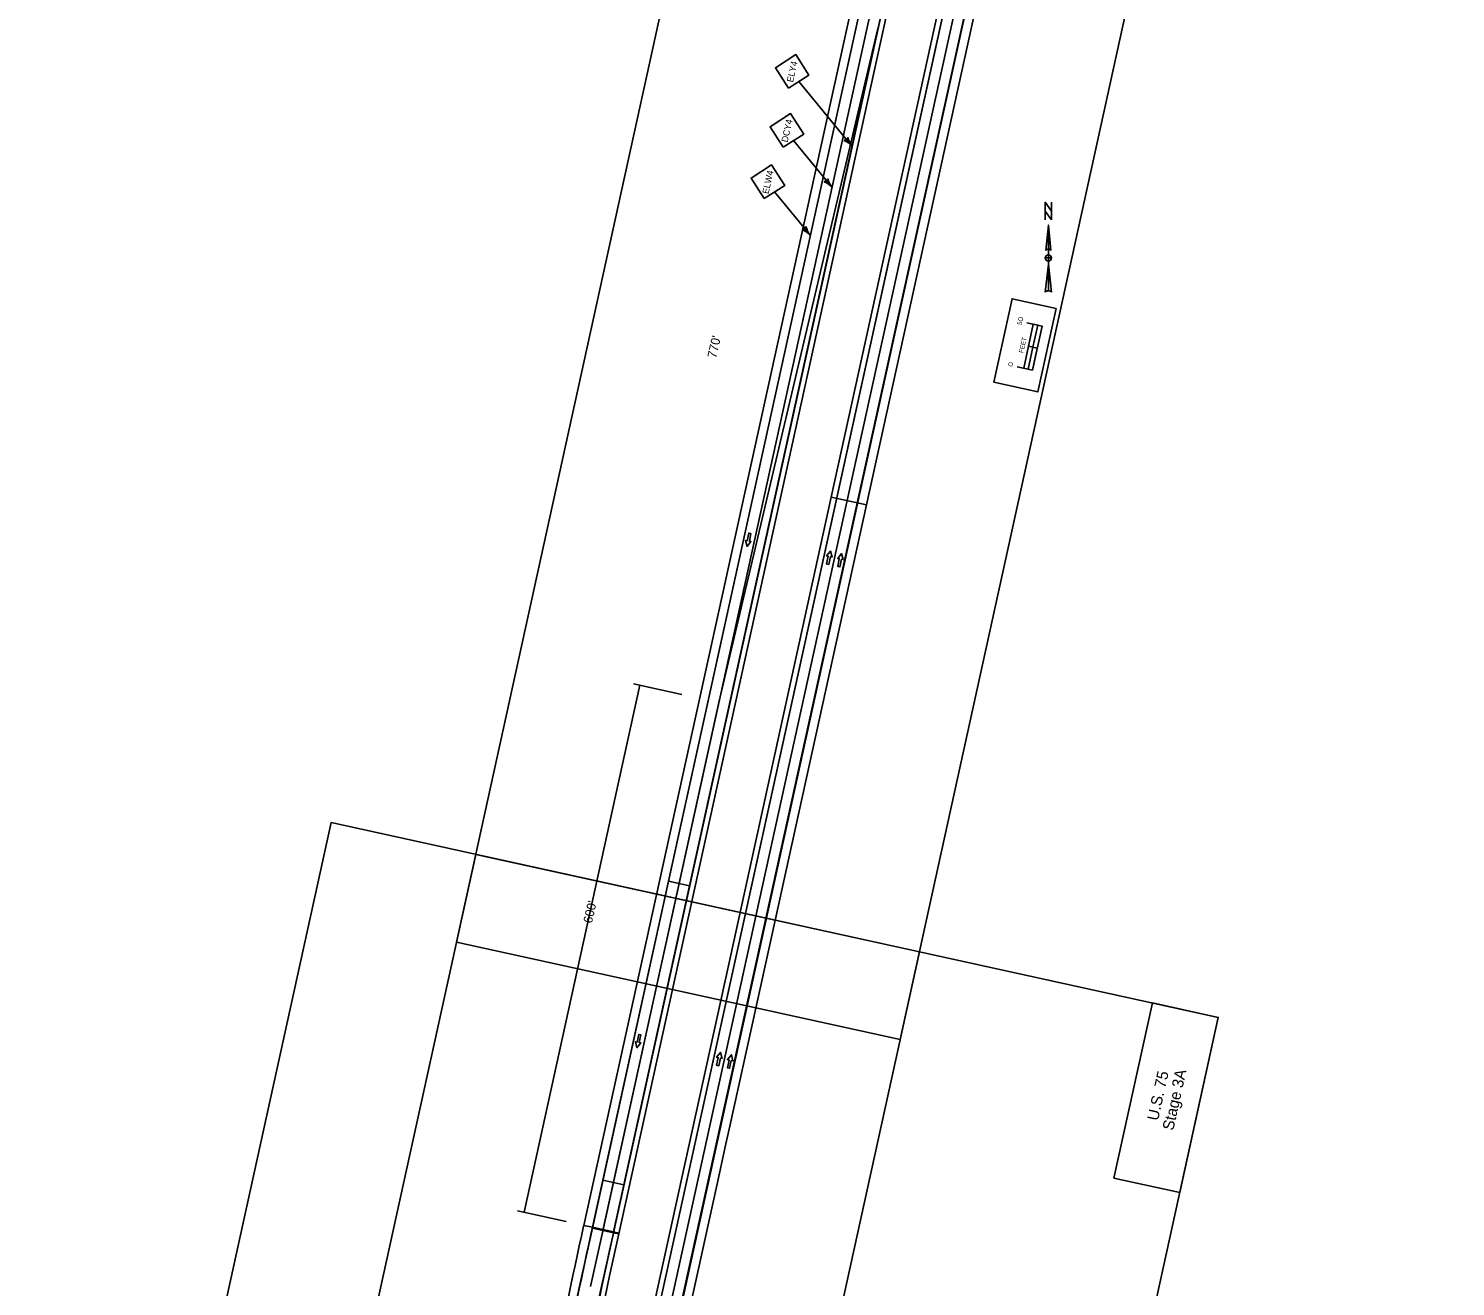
# Model space of a CAD drawing. Extents: x 14104283 to 14129344, y 8637090 to 8673339.
# Drawn here: x 14107490 to 14109077, y 8640895 to 8642294 of the extents above; entities that cross this region are included whole.
import ezdxf

# ---------------------------------------------------------------- set-up
doc = ezdxf.new("R2010")
doc.units = 0
for name, color, linetype in [('Cell', 7, 'Continuous'), ('Default', 7, 'Continuous'), ('dsnCellsNorthArrow', 7, 'Continuous'), ('dsnCellsScaleBlock', 7, 'Continuous'), ('dsnNonPlotable', 7, 'Continuous'), ('dsnPaintExistingBrokenLaneLineWhite', 7, 'Continuous'), ('dsnPaintPlaceBrokenLineWhite', 7, 'Continuous'), ('dsnPaintPlaceEdgeLineLeftYellow', 7, 'Continuous'), ('dsnPaintPlaceEdgeLineRightWhite', 7, 'Continuous'), ('dsnShadingPaved', 7, 'Continuous'), ('dsnStdLabel', 7, 'Continuous'), ('dsnStgShadingPrevPav', 7, 'Continuous'), ('dsnTextOverlapOdd', 7, 'Continuous')]:
    doc.layers.add(name, color=color, linetype=linetype)

msp = doc.modelspace()

# ---------------------------------------------------------------- linework, layer by layer
at = {"layer": 'Cell'}
for points in [[(14108291.3, 8641733.2), (14108293.7, 8641732.6), (14108291.9, 8641724.1), (14108293.7, 8641723.7), (14108289.3, 8641718.3), (14108287.6, 8641725), (14108289.4, 8641724.6)], [(14108380.2, 8641698.2), (14108377.7, 8641698.8), (14108379.6, 8641707.3), (14108377.8, 8641707.7), (14108382.2, 8641713.1), (14108383.9, 8641706.4), (14108382.1, 8641706.8)], [(14108392.5, 8641695.5), (14108390.1, 8641696.1), (14108391.9, 8641704.6), (14108390.1, 8641705), (14108394.5, 8641710.4), (14108396.2, 8641703.7), (14108394.4, 8641704.1)], [(14108168.9, 8641175.7), (14108171.3, 8641175.2), (14108169.5, 8641166.6), (14108171.3, 8641166.2), (14108166.9, 8641160.8), (14108165.2, 8641167.6), (14108167, 8641167.2)], [(14108257.9, 8641140.7), (14108255.4, 8641141.3), (14108257.3, 8641149.8), (14108255.5, 8641150.2), (14108259.8, 8641155.6), (14108261.6, 8641148.9), (14108259.7, 8641149.3)], [(14108269.9, 8641138.1), (14108267.5, 8641138.6), (14108269.3, 8641147.2), (14108267.5, 8641147.6), (14108271.9, 8641153), (14108273.6, 8641146.2), (14108271.8, 8641146.6)]]:
    msp.add_lwpolyline(points, close=True, dxfattribs=at)
for points in [[(14108289.4, 8641724.6), (14108287.6, 8641725), (14108289.3, 8641718.3), (14108293.7, 8641723.7), (14108291.9, 8641724.1), (14108293.7, 8641732.6), (14108291.3, 8641733.2), (14108289.4, 8641724.6)], [(14108382.1, 8641706.8), (14108383.9, 8641706.4), (14108382.2, 8641713.1), (14108377.8, 8641707.7), (14108379.6, 8641707.3), (14108377.7, 8641698.8), (14108380.2, 8641698.2), (14108382.1, 8641706.8)], [(14108394.4, 8641704.1), (14108396.2, 8641703.7), (14108394.5, 8641710.4), (14108390.1, 8641705), (14108391.9, 8641704.6), (14108390.1, 8641696.1), (14108392.5, 8641695.5), (14108394.4, 8641704.1)], [(14108167, 8641167.2), (14108165.2, 8641167.6), (14108166.9, 8641160.8), (14108171.3, 8641166.2), (14108169.5, 8641166.6), (14108171.3, 8641175.2), (14108168.9, 8641175.7), (14108167, 8641167.2)], [(14108259.7, 8641149.3), (14108261.6, 8641148.9), (14108259.8, 8641155.6), (14108255.5, 8641150.2), (14108257.3, 8641149.8), (14108255.4, 8641141.3), (14108257.9, 8641140.7), (14108259.7, 8641149.3)], [(14108271.8, 8641146.6), (14108273.6, 8641146.2), (14108271.9, 8641153), (14108267.5, 8641147.6), (14108269.3, 8641147.2), (14108267.5, 8641138.6), (14108269.9, 8641138.1), (14108271.8, 8641146.6)]]:
    msp.add_lwpolyline(points, dxfattribs=at)
at = {"layer": 'Default'}
for p, q in [((14108258, 8641544.6), (14108434.9, 8642294.1)), ((14108213.8, 8641343.5), (14108258, 8641544.6)), ((14108117.4, 8640960.3), (14108202.1, 8641346.1)), ((14108202.1, 8641346.1), (14108213.8, 8641343.5)), ((14108213.8, 8641343.5), (14108129.1, 8640957.7)), ((14108117.4, 8640960.4), (14108103.5, 8640897.2)), ((14108103.7, 8640898), (14108117.6, 8640961.2)), ((14108129.3, 8640958.6), (14108115.4, 8640895.4)), ((14108140.9, 8640955.2), (14108117.4, 8640960.4)), ((14108127, 8640892.1), (14108140.9, 8640955.2))]:
    msp.add_line(p, q, dxfattribs=at)
msp.add_lwpolyline([(14108976.3, 8644903.9), (14108611.6, 8643210.2), (14108202.1, 8641346.1)], dxfattribs=at)
msp.add_lwpolyline([(14108129.1, 8640957.7), (14108141, 8640956), (14108434.9, 8642294.1), (14108258, 8641544.6), (14108129.3, 8640958.6)], close=True, dxfattribs=at)
for centre, end in [((14117394.1, 8638857.1), 171.32599), ((14117394, 8638856.3), 169.43633)]:
    msp.add_arc(centre, 9512, 167.61021, end, dxfattribs=at)
at = {"layer": 'dsnCellsNorthArrow'}
for p, q in [((14108624.4, 8642075.6), (14108627.2, 8642047.4)), ((14108624.4, 8642075.6), (14108624.4, 8642002.4)), ((14108621.6, 8642047.4), (14108621.6, 8642047.4)), ((14108621.7, 8642047.7), (14108622.2, 8642048.3)), ((14108620.9, 8642001), (14108624.4, 8642032)), ((14108624.4, 8642035.5), (14108624.4, 8642035.5))]:
    msp.add_line(p, q, dxfattribs=at)
msp.add_lwpolyline([(14108627.9, 8642081.3), (14108620.9, 8642091.1), (14108620.9, 8642101), (14108627.9, 8642091.1)], close=True, dxfattribs=at)
for points in [[(14108620.9, 8642081.3), (14108620.9, 8642101), (14108627.9, 8642091.1), (14108627.9, 8642101)], [(14108621.6, 8642047.4), (14108624.4, 8642075.6), (14108624.4, 8642048.9)], [(14108624.4, 8642035.5), (14108624.4, 8642039), (14108620.9, 8642039)], [(14108627.9, 8642039), (14108624.4, 8642039), (14108624.4, 8642042.5)], [(14108624.4, 8642002.4), (14108624.4, 8642032), (14108627.9, 8642001)]]:
    msp.add_lwpolyline(points, dxfattribs=at)
for centre, radius, start, end in [((14108624.4, 8642045.3), 3.52, 90.0204, 143.1257), ((14108624.4, 8642045.3), 3.52, 36.8481, 90.0218), ((14108624.4, 8642039), 3.52, 90, 180), ((14108624.4, 8642039), 3.52, 180, 270), ((14108624.4, 8642039), 3.52, 0, 90), ((14108624.4, 8642039), 3.52, 270, 360), ((14108624.4, 8641997.3), 5.1, 89.9894, 133.619), ((14108624.4, 8641997.3), 5.11, 46.4021, 90.0006)]:
    msp.add_arc(centre, radius, start, end, dxfattribs=at)
at = {"layer": 'dsnCellsScaleBlock'}
msp.add_line((14108612, 8641938.8), (14108602.3, 8641940.9), dxfattribs=at)
msp.add_line((14108612, 8641938.8), (14108602.3, 8641940.9), dxfattribs=at)
for points in [[(14108612.6, 8641890), (14108563.8, 8641900.8), (14108584.1, 8641993.6), (14108633, 8641982.8)], [(14108563.8, 8641900.8), (14108584.1, 8641993.6), (14108633, 8641982.8), (14108612.6, 8641890)], [(14108612.6, 8641890), (14108563.8, 8641900.8), (14108584.1, 8641993.6), (14108633, 8641982.8)], [(14108607.1, 8641939.9), (14108612.5, 8641964.3), (14108607.6, 8641965.4), (14108602.3, 8641940.9)], [(14108606.7, 8641914.4), (14108612, 8641938.8), (14108607.1, 8641939.9), (14108601.8, 8641915.5)]]:
    msp.add_lwpolyline(points, close=True, dxfattribs=at)
for points in [[(14108589.6, 8641918.1), (14108606.7, 8641914.4), (14108617.4, 8641963.2), (14108600.3, 8641967)], [(14108596.9, 8641916.5), (14108607.6, 8641965.4)]]:
    msp.add_lwpolyline(points, dxfattribs=at)
at = {"layer": 'dsnNonPlotable'}
for points in [[(14107966.2, 8641278.2), (14108302.6, 8642809.2), (14108795.9, 8642700.9), (14108459.5, 8641169.9)], [(14107490.5, 8639880.3), (14107826.8, 8641411.3), (14108813.3, 8641194.5), (14108476.9, 8639663.5)], [(14107651.3, 8639844.9), (14107987.7, 8641375.9), (14108480.9, 8641267.5), (14108144.5, 8639736.6)]]:
    msp.add_lwpolyline(points, close=True, dxfattribs=at)
at = {"layer": 'dsnPaintExistingBrokenLaneLineWhite'}
msp.add_line((14108213.8, 8641343.5), (14108623.3, 8643207.7), dxfattribs=at)
at = {"layer": 'dsnPaintPlaceBrokenLineWhite'}
for p, q in [((14108129.1, 8640957.7), (14108213.8, 8641343.5)), ((14108189.8, 8640810.1), (14108306.4, 8641340.7)), ((14108115.4, 8640895.4), (14108129.3, 8640958.6))]:
    msp.add_line(p, q, dxfattribs=at)
msp.add_lwpolyline([(14108306.4, 8641340.7), (14108389, 8641717), (14108712.3, 8643188.3), (14108894.6, 8644035.3), (14109077, 8644882.2)], dxfattribs=at)
at = {"layer": 'dsnPaintPlaceEdgeLineLeftYellow'}
for p, q in [((14108199.6, 8640910.3), (14108700.5, 8643190.8)), ((14108225.5, 8641340.9), (14108141, 8640956))]:
    msp.add_line(p, q, dxfattribs=at)
msp.add_lwpolyline([(14108999.8, 8644898.8), (14108635.1, 8643205.1), (14108225.5, 8641340.9)], dxfattribs=at)
msp.add_arc((14117586.5, 8638823.8), 9683.1, 167.27944, 171.3032, dxfattribs=at)
at = {"layer": 'dsnPaintPlaceEdgeLineRightWhite'}
for p, q in [((14108201.6, 8640807.6), (14108724, 8643185.7)), ((14108202.1, 8641346.1), (14108117.6, 8640961.2)), ((14108117.6, 8640961.2), (14108103.7, 8640898))]:
    msp.add_line(p, q, dxfattribs=at)
msp.add_lwpolyline([(14108976.3, 8644903.9), (14108611.6, 8643210.2), (14108202.1, 8641346.1)], dxfattribs=at)
msp.add_arc((14117394.1, 8638857.1), 9512, 167.61021, 168.00312, dxfattribs=at)
at = {"layer": 'dsnShadingPaved'}
for p, q in [((14108700.5, 8643190.9), (14108199.6, 8640910.3)), ((14108200.8, 8640807.8), (14108724, 8643185.7)), ((14108199.6, 8640910.3), (14108178.1, 8640812.5))]:
    msp.add_line(p, q, dxfattribs=at)
at = {"layer": 'dsnStdLabel'}
for p, q in [((14108346.8, 8642235.1), (14108406.2, 8642163.1)), ((14108340.9, 8642169.5), (14108384.1, 8642117.2)), ((14108319.8, 8642112.4), (14108359.8, 8642063.9)), ((14108170.1, 8641563.9), (14108041.4, 8640977.9)), ((14108162.9, 8641565.5), (14108217, 8641553.6)), ((14108034.1, 8640979.5), (14108088.3, 8640967.6))]:
    msp.add_line(p, q, dxfattribs=at)
for points in [[(14108335.4, 8642227.8), (14108358.2, 8642242.4), (14108343.6, 8642265.1), (14108320.9, 8642250.6)], [(14108329.6, 8642162.2), (14108352.3, 8642176.8), (14108337.8, 8642199.5), (14108315, 8642185)], [(14108308.5, 8642105.1), (14108331.2, 8642119.7), (14108316.6, 8642142.4), (14108293.9, 8642127.9)]]:
    msp.add_lwpolyline(points, close=True, dxfattribs=at)
for centre, radius, start, end in [((14108393.7, 8642177.8), 8.86, 292.8385, 328.307), ((14108388.7, 8642148.2), 22.9, 40.5727, 68.6439), ((14108423.6, 8642178.1), 22.9, 192.5015, 220.5728), ((14108371.6, 8642131.8), 8.86, 292.8385, 328.307), ((14108366.7, 8642102.3), 22.9, 40.5727, 68.6439), ((14108401.5, 8642132.1), 22.9, 192.5015, 220.5728), ((14108347.3, 8642078.6), 8.86, 292.8385, 328.307), ((14108342.4, 8642049), 22.9, 40.5727, 68.6439), ((14108377.2, 8642078.9), 22.9, 192.5015, 220.5728)]:
    msp.add_arc(centre, radius, start, end, dxfattribs=at)
at = {"layer": 'dsnStgShadingPrevPav'}
for p, q in [((14108107.8, 8640963.3), (14108601.8, 8643212.3)), ((14108611.6, 8643210.2), (14108117.6, 8640961.2)), ((14108694.7, 8643192.1), (14108383, 8641773.2)), ((14108422, 8641764.6), (14108733.8, 8643183.6)), ((14108383, 8641773.2), (14108422, 8641764.6)), ((14108225.5, 8641340.9), (14108202.1, 8641346.1)), ((14108107.8, 8640963.3), (14108107.6, 8640962.4)), ((14108117.6, 8640961.2), (14108107.8, 8640963.3)), ((14108117.6, 8640961.2), (14108107.8, 8640963.3)), ((14108117.4, 8640960.3), (14108117.6, 8640961.2)), ((14108140.8, 8640955.1), (14108141, 8640956)), ((14108140.8, 8640955.1), (14108146.7, 8640953.8)), ((14108141, 8640956), (14108146.9, 8640954.7)), ((14108146.9, 8640954.7), (14108146.7, 8640953.8))]:
    msp.add_line(p, q, dxfattribs=at)
for points in [[(14108999.8, 8644898.8), (14108817.4, 8644052), (14108635.1, 8643205.1), (14108387.9, 8642080.1), (14108140.8, 8640955.1)], [(14108202.1, 8641346.1), (14108611.6, 8643210.2), (14108976.3, 8644903.9)], [(14108999.8, 8644898.8), (14108635.1, 8643205.1), (14108225.5, 8641340.9)], [(14108146.7, 8640953.8), (14108640.9, 8643203.9), (14109005.6, 8644897.6)], [(14108117.4, 8640960.3), (14108117.6, 8640961.2), (14108141, 8640956), (14108140.8, 8640955.1)]]:
    msp.add_lwpolyline(points, dxfattribs=at)
for points in [[(14108081.5, 8640400.9), (14108123.3, 8640591.3), (14108126.6, 8640606), (14108216.7, 8641016.2), (14108268.2, 8641250.6), (14108383, 8641773.2), (14108422, 8641764.6), (14108309.4, 8641251.8), (14108270.2, 8641073.5), (14108265.9, 8641054), (14108255.7, 8641007.6), (14108202.1, 8640763.4), (14108120.6, 8640392.3)], [(14108129.1, 8641013.6), (14108202.1, 8641346.1), (14108225.5, 8641340.9), (14108152.5, 8641008.5)], [(14108141, 8640956), (14108117.6, 8640961.2), (14108129.1, 8641013.6), (14108152.5, 8641008.5)]]:
    msp.add_lwpolyline(points, close=True, dxfattribs=at)
for radius, end in [(9488, 172.22208), (9482, 172.22208), (9522, 168.68895), (9512, 168.32826), (9512, 168.32826), (9488, 168.32826)]:
    msp.add_arc((14117407.8, 8638919.4), radius, 167.61021, end, dxfattribs=at)
at = {"layer": 'dsnTextOverlapOdd'}
for points in [[(14108813.3, 8641194.5), (14108770.5, 8640999.9), (14108697.3, 8641016), (14108740.1, 8641210.6)], [(14108697.3, 8641016), (14108740.1, 8641210.6), (14108813.3, 8641194.5), (14108770.5, 8640999.9)]]:
    msp.add_lwpolyline(points, close=True, dxfattribs=at)

# ---------------------------------------------------------------- texts
at = {"layer": 'dsnCellsScaleBlock'}
for s, p in [('5O', (14108594.6, 8641964.1)), ('FEET', (14108596.4, 8641933)), ('O', (14108584.3, 8641917.6))]:
    msp.add_text(s, height=5, rotation=77.6078, dxfattribs=at).set_placement(p)
at = {"layer": 'dsnStdLabel'}
for s, height, rotation, p in [('ELY4', 7.2, 77.6078, (14108340.4, 8642233.9)), ('DCY4', 7.2, 77.6078, (14108334.4, 8642167.2)), ('ELW4', 7.2, 77.6078, (14108313.2, 8642109.8)), ("770'", 10, 77.0531, (14108254.8, 8641927)), ("600'", 10, 77.0531, (14108116.8, 8641298.6))]:
    msp.add_text(s, height=height, rotation=rotation, dxfattribs=at).set_placement(p)
at = {"layer": 'dsnTextOverlapOdd'}
for s, p in [('U.S. 75', (14108746.3, 8641079)), ('Stage 3A', (14108763.2, 8641068.2))]:
    msp.add_text(s, height=12.5, rotation=77.6078, dxfattribs=at).set_placement(p)

doc.saveas('drawing.dxf')
